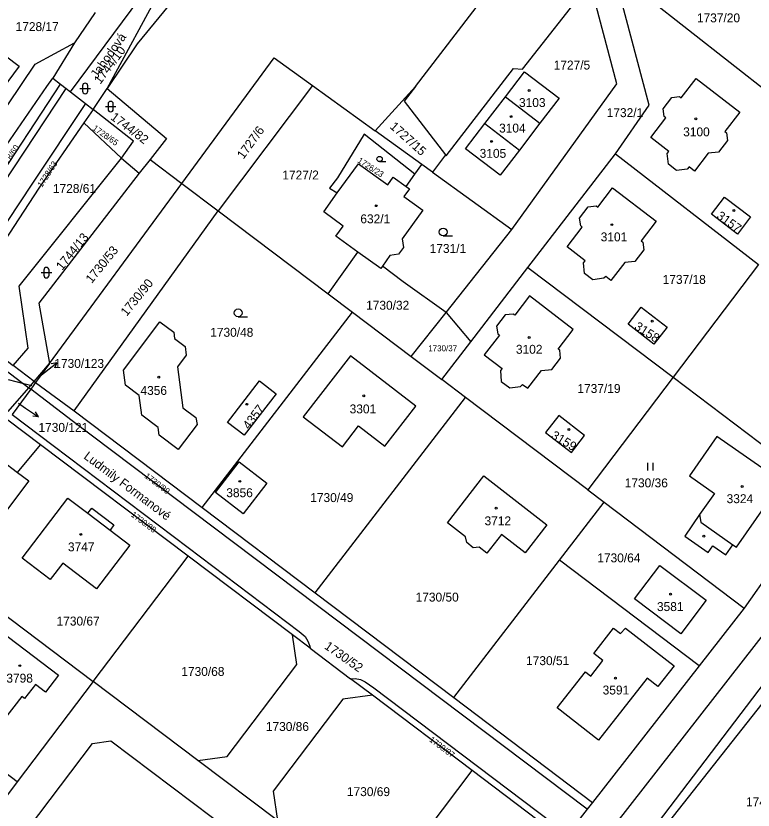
# Model space of a CAD drawing. Extents: x -679220 to -673243, y -1075091 to -1066557.
# Drawn here: x -677014 to -676873.4, y -1072325 to -1072173.6 of the extents above; entities that cross this region are included whole.
import ezdxf

# ---------------------------------------------------------------- set-up
doc = ezdxf.new("R2010")
doc.units = 0
for name, color, linetype in [('Hranice parcel', 7, 'Continuous'), ('Parcelní čísla', 7, 'Continuous'), ('Pop  PČ popisy', 7, 'Continuous'), ('Vnitřní kresba', 7, 'Continuous'), ('Značky budov', 7, 'Continuous'), ('Značky kultur', 7, 'Continuous')]:
    doc.layers.add(name, color=color, linetype=linetype)

msp = doc.modelspace()

# ---------------------------------------------------------------- linework, layer by layer
at = {"layer": 'Hranice parcel'}
for p, q in [((-676937.78, -1072187.06), (-676885.9, -1072119.34)), ((-676868.31, -1072190), (-676899.96, -1072165.14)), ((-676998.86, -1072172.9), (-677002.77, -1072178.71)), ((-677002.77, -1072178.71), (-677006.93, -1072185.42)), ((-677006.93, -1072185.42), (-677005.45, -1072186.58)), ((-677005.45, -1072186.58), (-677004.4, -1072187.4)), ((-677004.4, -1072187.4), (-677003.56, -1072188.05)), ((-677003.56, -1072188.05), (-677000.68, -1072190.31)), ((-676999.25, -1072191.43), (-676996.56, -1072187.43)), ((-676957.44, -1072186.84), (-676975.41, -1072210.74)), ((-676957.44, -1072186.84), (-676945.48, -1072195.49)), ((-676945.48, -1072195.49), (-676937.78, -1072187.06)), ((-676924.56, -1072194.1), (-676920.66, -1072189.01)), ((-676920.66, -1072189.01), (-676914.1, -1072194.06)), ((-677000.68, -1072190.31), (-676999.25, -1072191.43)), ((-676999.25, -1072191.43), (-677000.98, -1072193.99)), ((-677000.98, -1072193.99), (-676993.8, -1072200.73)), ((-676924.56, -1072194.1), (-676917.99, -1072199.15)), ((-676914.1, -1072194.06), (-676917.99, -1072199.15)), ((-676936.58, -1072201.92), (-676945.48, -1072195.49)), ((-676932.07, -1072200.1), (-676934.58, -1072203.37)), ((-676916.37, -1072221.57), (-676899.68, -1072199.86)), ((-676899.68, -1072199.86), (-676872.43, -1072221.01)), ((-676993.8, -1072200.73), (-676990.45, -1072203.57)), ((-676988.38, -1072200.94), (-676990.45, -1072203.57)), ((-676988.38, -1072200.94), (-676982.32, -1072205.52)), ((-676937.89, -1072203.74), (-676936.58, -1072201.92)), ((-676934.58, -1072203.37), (-676936.58, -1072201.92)), ((-676934.58, -1072203.37), (-676919.44, -1072214.32)), ((-676939.58, -1072206.09), (-676937.89, -1072203.74)), ((-677007.53, -1072239.86), (-676982.32, -1072205.52)), ((-676982.32, -1072205.52), (-676975.41, -1072210.74)), ((-677002.87, -1072248.9), (-676975.41, -1072210.74)), ((-676975.41, -1072210.74), (-676954.45, -1072226.57)), ((-676931.93, -1072230.12), (-676919.44, -1072214.32)), ((-676954.45, -1072226.57), (-676948.76, -1072218.62)), ((-676927.27, -1072235.75), (-676916.37, -1072221.57)), ((-676916.37, -1072221.57), (-676888.67, -1072242.5)), ((-676872.43, -1072221.01), (-676888.67, -1072242.5)), ((-676954.45, -1072226.57), (-676949.79, -1072230.09)), ((-676978.44, -1072267.35), (-676949.79, -1072230.09)), ((-676949.79, -1072230.09), (-676938.6, -1072238.55)), ((-676938.6, -1072238.55), (-676931.93, -1072230.12)), ((-676931.93, -1072230.12), (-676927.27, -1072235.75)), ((-676932.8, -1072242.93), (-676927.27, -1072235.75)), ((-676938.6, -1072238.55), (-676932.8, -1072242.93)), ((-677010.47, -1072243.28), (-677014.49, -1072240.22)), ((-677010.47, -1072243.28), (-677007.53, -1072239.86)), ((-677007.53, -1072239.86), (-677010.19, -1072243.49)), ((-676888.67, -1072242.5), (-676904.92, -1072263.99)), ((-676888.67, -1072242.5), (-676859.7, -1072264.4)), ((-677011.5, -1072244.49), (-677010.47, -1072243.28)), ((-677010.19, -1072243.49), (-677011.13, -1072244.77)), ((-677010.47, -1072243.28), (-677010.19, -1072243.49)), ((-677010.19, -1072243.49), (-677002.87, -1072248.9)), ((-676928.25, -1072246.37), (-676932.8, -1072242.93)), ((-677015.41, -1072249.05), (-677011.5, -1072244.49)), ((-677011.13, -1072244.77), (-677014.68, -1072249.6)), ((-677011.5, -1072244.49), (-677011.13, -1072244.77)), ((-676956.9, -1072283.63), (-676928.25, -1072246.37)), ((-676904.92, -1072263.99), (-676928.25, -1072246.37)), ((-677002.87, -1072248.9), (-676978.44, -1072267.35)), ((-677009.25, -1072255.35), (-677015.46, -1072250.66)), ((-677013.62, -1072260.65), (-677009.25, -1072255.35)), ((-676981.14, -1072276.59), (-677009.25, -1072255.35)), ((-676904.92, -1072263.99), (-676901.84, -1072266.32)), ((-676859.7, -1072264.4), (-676875.12, -1072286.5)), ((-676910.35, -1072277.39), (-676901.84, -1072266.32)), ((-676901.84, -1072266.32), (-676875.12, -1072286.5)), ((-676978.44, -1072267.35), (-676956.9, -1072283.63)), ((-676999.23, -1072300.52), (-676981.14, -1072276.59)), ((-676961.22, -1072291.64), (-676981.14, -1072276.59)), ((-676930.48, -1072303.58), (-676910.35, -1072277.39)), ((-676883.74, -1072297.55), (-676910.35, -1072277.39)), ((-677028.33, -1072278.52), (-676999.23, -1072300.52)), ((-676956.9, -1072283.63), (-676930.48, -1072303.58)), ((-676875.12, -1072286.5), (-676883.74, -1072297.55)), ((-676957.87, -1072294.17), (-676961.22, -1072291.64)), ((-676957.87, -1072294.17), (-676950.18, -1072299.98)), ((-676883.74, -1072297.55), (-676904.04, -1072323.56)), ((-677013.7, -1072319.67), (-677039.8, -1072299.95)), ((-676946.01, -1072303.12), (-676950.18, -1072299.98)), ((-676999.23, -1072300.52), (-677013.7, -1072319.67)), ((-676979.28, -1072315.59), (-676999.23, -1072300.52)), ((-676926.98, -1072317.5), (-676946.01, -1072303.12)), ((-676869.87, -1072302.33), (-676891.88, -1072330.24)), ((-676930.48, -1072303.58), (-676904.04, -1072323.56)), ((-676964.12, -1072327.04), (-676979.28, -1072315.59)), ((-676945.08, -1072341.44), (-676926.98, -1072317.5)), ((-676909.57, -1072330.65), (-676926.98, -1072317.5)), ((-677013.7, -1072319.67), (-677028.16, -1072338.82)), ((-676904.04, -1072323.56), (-676905.06, -1072324.86)), ((-676905.06, -1072324.86), (-676908.8, -1072329.65))]:
    msp.add_line(p, q, dxfattribs=at)
for points in [[(-677003.56, -1072188.05), (-676937.07, -1072098.47), (-676924.77, -1072082.25), (-676901.08, -1072050.53), (-676900.33, -1072051.15)], [(-676996.56, -1072187.43), (-676985.94, -1072167.77), (-676927.29, -1072088.05)], [(-676924.4, -1072090.21), (-676960.77, -1072142.26), (-676990.83, -1072178.91), (-676996.56, -1072187.43)], [(-676899.68, -1072199.86), (-676893.25, -1072190.57), (-676899.96, -1072165.14)], [(-676932.07, -1072200.1), (-676931.93, -1072200.28), (-676919.14, -1072183.61), (-676917.4, -1072183.73), (-676904.51, -1072167.26)], [(-676919.44, -1072214.32), (-676899.4, -1072186.54), (-676904.51, -1072167.26)], [(-677022.43, -1072175.06), (-677023.03, -1072175.85), (-677013.34, -1072183.15), (-677017.74, -1072189.03), (-677020.94, -1072186.65), (-677024.75, -1072191.65), (-677029.79, -1072187.85), (-677030, -1072188.09), (-677035.87, -1072183.69), (-677026.86, -1072171.73), (-677022.43, -1072175.06)], [(-677026.1, -1072206.25), (-677010.31, -1072182.77), (-677002.77, -1072178.71)], [(-676982.32, -1072205.52), (-676964.73, -1072181.57), (-676957.44, -1072186.84)], [(-676920.66, -1072189.01), (-676917, -1072184.22), (-676910.43, -1072189.26), (-676914.1, -1072194.06)], [(-677023.17, -1072209.06), (-677022.36, -1072209.08), (-677021.37, -1072208.84), (-677020.43, -1072208.43), (-677019.61, -1072207.8), (-677018.91, -1072207.08), (-677005.45, -1072186.58)], [(-677021.37, -1072206.38), (-677008.05, -1072187.02), (-677006.93, -1072185.42)], [(-676890.1, -1072193.02), (-676890.37, -1072192.78), (-676890.58, -1072191.29), (-676888.94, -1072189.16), (-676887.45, -1072188.97), (-676887.16, -1072189.21), (-676884.32, -1072185.52), (-676875.99, -1072191.91), (-676878.86, -1072195.65), (-676878.54, -1072195.88), (-676878.34, -1072197.36), (-676880.03, -1072199.55), (-676881.99, -1072199.74), (-676884.63, -1072203.18), (-676885.66, -1072202.38), (-676885.98, -1072202.79), (-676888.05, -1072203.05), (-676889.59, -1072201.87), (-676889.82, -1072199.8), (-676889.53, -1072199.42), (-676892.96, -1072196.78), (-676890.1, -1072193.02)], [(-677041.29, -1072239.09), (-677020.3, -1072211.54), (-677004.4, -1072187.4)], [(-676996.56, -1072187.43), (-676985.27, -1072196.98), (-676988.38, -1072200.94)], [(-676937.78, -1072187.06), (-676939.93, -1072189.86), (-676932.07, -1072200.1)], [(-676904.77, -1072334.29), (-676870.34, -1072290.1), (-676818.72, -1072215.8), (-676800.09, -1072189.36)], [(-677000.68, -1072190.31), (-677010.81, -1072205.46), (-677025.05, -1072227.04), (-677025.58, -1072227.92), (-677026.06, -1072228.81), (-677026.31, -1072229.79), (-677026.34, -1072230.8), (-677026.21, -1072231.82), (-677025.88, -1072232.78), (-677025.36, -1072233.67), (-677024.7, -1072234.47), (-677011.5, -1072244.49)], [(-676993.8, -1072200.73), (-676991.56, -1072197.46), (-676999.25, -1072191.43)], [(-677000.98, -1072193.99), (-677009.55, -1072206.46), (-677019.04, -1072220.85), (-677024.42, -1072229.04), (-677024.78, -1072230), (-677024.76, -1072230.97), (-677024.5, -1072231.92), (-677024.01, -1072232.8), (-677023.32, -1072233.51), (-677014.49, -1072240.22)], [(-676917.99, -1072199.15), (-676921.68, -1072203.94), (-676928.23, -1072198.9), (-676924.56, -1072194.1)], [(-676937.89, -1072203.74), (-676947.59, -1072196.14), (-676952.65, -1072204.47), (-676954.21, -1072206.43), (-676952.7, -1072207.35)], [(-677014.49, -1072240.22), (-677011.6, -1072236.95), (-677013.33, -1072225.14), (-676993.8, -1072200.73)], [(-676952.7, -1072207.35), (-676948.66, -1072201.76), (-676943.09, -1072205.77), (-676942.03, -1072204.31), (-676939.58, -1072206.09)], [(-676990.45, -1072203.57), (-677009.57, -1072228.38), (-677007.53, -1072239.86)], [(-676939.58, -1072206.09), (-676938.96, -1072206.54), (-676940.01, -1072207.99), (-676936.36, -1072210.64), (-676940.32, -1072216.11), (-676940.09, -1072217.74), (-676941.03, -1072219.03), (-676942.65, -1072219.3), (-676944.1, -1072221.31)], [(-676901.53, -1072223.27), (-676901.92, -1072223.61), (-676903.99, -1072223.94), (-676905.55, -1072222.71), (-676905.77, -1072220.66), (-676905.48, -1072220.26), (-676908.89, -1072217.63), (-676906.02, -1072213.86), (-676906.3, -1072213.62), (-676906.56, -1072212.15), (-676904.89, -1072210), (-676903.37, -1072209.8), (-676903.06, -1072210.02), (-676900.26, -1072206.35), (-676891.93, -1072212.75), (-676894.78, -1072216.47), (-676894.48, -1072216.72), (-676894.29, -1072218.2), (-676895.96, -1072220.4), (-676897.9, -1072220.58), (-676900.56, -1072224.01), (-676901.53, -1072223.27)], [(-676948.76, -1072218.62), (-676952.95, -1072215.6), (-676951.55, -1072213.67), (-676955.29, -1072210.94), (-676952.7, -1072207.35)], [(-676873.92, -1072211.88), (-676876.42, -1072215.19), (-676881.35, -1072211.4), (-676878.9, -1072208.15), (-676873.92, -1072211.88)], [(-676944.1, -1072221.31), (-676944.42, -1072221.76), (-676948.76, -1072218.62)], [(-676931.93, -1072230.12), (-676940.17, -1072224.32), (-676944.1, -1072221.31)], [(-676921.58, -1072241.22), (-676921.46, -1072243.29), (-676919.84, -1072244.51), (-676917.76, -1072244.27), (-676917.39, -1072243.87), (-676916.41, -1072244.6), (-676913.78, -1072241.23), (-676911.81, -1072241.02), (-676910.14, -1072238.87), (-676910.3, -1072237.35), (-676910.58, -1072237.12), (-676907.73, -1072233.39), (-676916.04, -1072226.98), (-676918.88, -1072230.64), (-676919.16, -1072230.44), (-676920.7, -1072230.61), (-676922.36, -1072232.73), (-676922.09, -1072234.21), (-676921.8, -1072234.44), (-676924.71, -1072238.2), (-676921.29, -1072240.84), (-676921.58, -1072241.22)], [(-676889.83, -1072232.95), (-676892.35, -1072236.18), (-676897.25, -1072232.37), (-676894.77, -1072229.1), (-676889.83, -1072232.95)], [(-676990.46, -1072245.98), (-676993.06, -1072244.01), (-676993.47, -1072241.13), (-676986.51, -1072231.94), (-676983.88, -1072233.91), (-676983.72, -1072235.09), (-676981.68, -1072236.65), (-676981.49, -1072238.27), (-676983.18, -1072240.51), (-676982.12, -1072248.29), (-676979.64, -1072250.17), (-676979.43, -1072251.49), (-676983.03, -1072256.26), (-676986.62, -1072253.51), (-676986.81, -1072252.06), (-676989.93, -1072249.74), (-676990.46, -1072245.98)], [(-676900.59, -1072339.27), (-676865.59, -1072293.33), (-676821.22, -1072232.97)], [(-676950.19, -1072238.42), (-676959.18, -1072250.03), (-676951.72, -1072255.78), (-676948.65, -1072251.77), (-676943.61, -1072255.64), (-676937.73, -1072248.01), (-676950.19, -1072238.42)], [(-676964.32, -1072245.64), (-676970.45, -1072253.56), (-676973.61, -1072251.11), (-676967.5, -1072243.19), (-676964.32, -1072245.64)], [(-676905.06, -1072324.86), (-676980.24, -1072268.15), (-677003.21, -1072250.78), (-677011.13, -1072244.77)], [(-677014.68, -1072249.6), (-677006.87, -1072255.49), (-676981.13, -1072274.94), (-676959.99, -1072291), (-676958.83, -1072291.96), (-676958.3, -1072292.81), (-676957.95, -1072293.75), (-676957.87, -1072294.17)], [(-676908.07, -1072256.82), (-676905.56, -1072253.61), (-676910.49, -1072249.76), (-676912.99, -1072253.05), (-676908.07, -1072256.82)], [(-676870.91, -1072266.7), (-676871.23, -1072266.48), (-676868.22, -1072262.25), (-676880.35, -1072253.8), (-676885.54, -1072261.32), (-676880.82, -1072264.69), (-676883.67, -1072268.69), (-676886.47, -1072272.81), (-676882, -1072275.9), (-676881.11, -1072274.65), (-676878.64, -1072276.36), (-676877.29, -1072274.43), (-676876.63, -1072274.89), (-676870.91, -1072266.7)], [(-677020.74, -1072269.31), (-677023.47, -1072267.21), (-677016.66, -1072258.36), (-677013.62, -1072260.65)], [(-676975.9, -1072264.49), (-676971.42, -1072258.62), (-676966.12, -1072262.67), (-676970.61, -1072268.54), (-676975.9, -1072264.49)], [(-677013.62, -1072260.65), (-677011.49, -1072262.26), (-677018.3, -1072271.19), (-677020.74, -1072269.31)], [(-676926.82, -1072274.99), (-676928, -1072274.03), (-676928.24, -1072272.95), (-676931.7, -1072270.27), (-676924.79, -1072261.29), (-676912.75, -1072270.63), (-676916.9, -1072275.97), (-676921.39, -1072272.46), (-676924.19, -1072276.03), (-676925.67, -1072274.92), (-676926.82, -1072274.99)], [(-677012.73, -1072276.99), (-677004.05, -1072265.54), (-677000.24, -1072268.42), (-676999.49, -1072267.43), (-676995.26, -1072270.64), (-676996.01, -1072271.63), (-676992.21, -1072274.5), (-676998.57, -1072282.86), (-677004.99, -1072277.95), (-677007.41, -1072281.08), (-677012.73, -1072276.99)], [(-676891.21, -1072278.38), (-676882.42, -1072285), (-676887.23, -1072291.4), (-676896.02, -1072284.77), (-676891.21, -1072278.38)], [(-677020.75, -1072295.82), (-677016.97, -1072290.85), (-677005.82, -1072299.3), (-677008.29, -1072302.54), (-677010.24, -1072301.07), (-677012.31, -1072303.76), (-677012.83, -1072303.35), (-677016.29, -1072307.91), (-677022.1, -1072303.49), (-677017.91, -1072297.98), (-677020.75, -1072295.82)], [(-676904.4, -1072299.48), (-676902.08, -1072296.5), (-676903.8, -1072295.15), (-676900.03, -1072290.31), (-676898.7, -1072291.34), (-676897.78, -1072290.34), (-676888.52, -1072297.55), (-676891.58, -1072301.47), (-676893.62, -1072299.88), (-676902.88, -1072311.7), (-676910.77, -1072305.54), (-676905.4, -1072298.69), (-676904.4, -1072299.48)], [(-676979.28, -1072315.59), (-676973.68, -1072314.81), (-676960.42, -1072297.25), (-676961.22, -1072291.64)], [(-676950.18, -1072299.98), (-676949.27, -1072299.96), (-676948.29, -1072300.16), (-676947.39, -1072300.57), (-676945.74, -1072301.71), (-676908.8, -1072329.65)], [(-676946.01, -1072303.12), (-676951.64, -1072303.88), (-676964.9, -1072321.44), (-676964.12, -1072327.04)], [(-677034.04, -1072358.2), (-676999.38, -1072312.31), (-676995.87, -1072311.82), (-676968.74, -1072332.31), (-676968.26, -1072335.81), (-677002.92, -1072381.7)]]:
    msp.add_lwpolyline(points, dxfattribs=at)
at = {"layer": 'Pop  PČ popisy'}
for p, q in [((-677008.49, -1072241.57), (-677006.12, -1072239.72)), ((-677006.12, -1072239.72), (-677007.22, -1072239.94)), ((-677006.12, -1072239.72), (-677006.61, -1072240.73)), ((-677009.45, -1072242.32), (-677008.49, -1072241.57)), ((-677012.42, -1072243.74), (-677015.33, -1072243.01)), ((-677010.9, -1072244.11), (-677012.42, -1072243.74)), ((-677013.48, -1072247.45), (-677012.13, -1072248.37)), ((-677012.13, -1072248.37), (-677009.64, -1072250.05)), ((-677009.64, -1072250.05), (-677010.75, -1072249.9)), ((-677009.64, -1072250.05), (-677010.19, -1072249.07))]:
    msp.add_line(p, q, dxfattribs=at)
at = {"layer": 'Vnitřní kresba'}
for p, q in [((-677000.24, -1072268.42), (-676996.01, -1072271.63)), ((-676883.67, -1072268.69), (-676883.4, -1072270.15)), ((-676883.4, -1072270.15), (-676877.29, -1072274.43))]:
    msp.add_line(p, q, dxfattribs=at)
at = {"layer": 'Značky budov'}
for centre in [(-676916.13, -1072187.81), (-676919.58, -1072192.78), (-676884.35, -1072193.21), (-676923.28, -1072197.5), (-676945.26, -1072209.78), (-676877.09, -1072210.68), (-676900.35, -1072213.39), (-676892.66, -1072231.8), (-676916.14, -1072234.91), (-676986.73, -1072242.46), (-676947.66, -1072246.03), (-676969.94, -1072247.64), (-676908.54, -1072252.46), (-676971.27, -1072262.34), (-676875.53, -1072263.31), (-676922.42, -1072267.44), (-677001.56, -1072272.46), (-676882.85, -1072272.8), (-676889.16, -1072283.85), (-677013.2, -1072297.49), (-676899.69, -1072299.87)]:
    msp.add_circle(centre, 0.175, dxfattribs=at)
at = {"layer": 'Značky kultur'}
for p, q in [((-677001.75, -1072187.41), (-676999.75, -1072187.41)), ((-677001.25, -1072186.91), (-677001.25, -1072187.91)), ((-677000.25, -1072187.91), (-677000.25, -1072186.91)), ((-676996.89, -1072190.87), (-676994.89, -1072190.87)), ((-676996.39, -1072190.37), (-676996.39, -1072191.37)), ((-676995.39, -1072191.37), (-676995.39, -1072190.37)), ((-676944.62, -1072201.37), (-676943.45, -1072201.37)), ((-676932.51, -1072215.54), (-676930.76, -1072215.54)), ((-677009.13, -1072222.54), (-677007.13, -1072222.54)), ((-677008.63, -1072222.04), (-677008.63, -1072223.04)), ((-677007.63, -1072223.04), (-677007.63, -1072222.04)), ((-676971.59, -1072230.96), (-676969.84, -1072230.96)), ((-676893.52, -1072260.29), (-676893.52, -1072258.79)), ((-676892.52, -1072260.29), (-676892.52, -1072258.79))]:
    msp.add_line(p, q, dxfattribs=at)
for centre, radius in [((-676944.63, -1072200.87), 0.502), ((-676932.51, -1072214.79), 0.75), ((-676971.59, -1072230.21), 0.75)]:
    msp.add_circle(centre, radius, dxfattribs=at)
for centre, start, end in [((-677000.75, -1072186.91), 0, 180), ((-677000.75, -1072187.91), 180, 359.9879), ((-676995.89, -1072190.37), 0, 180), ((-676995.89, -1072191.37), 180, 359.9879), ((-677008.13, -1072222.04), 0, 180), ((-677008.13, -1072223.04), 180, 359.9879)]:
    msp.add_arc(centre, 0.5, start, end, dxfattribs=at)

# ---------------------------------------------------------------- texts
at = {"layer": 'Parcelní čísla'}
for s, height, p in [('1737/20', 1.7, (-676884.15, -1072174.8)), ('1728/17', 1.7, (-677014.01, -1072176.47)), ('1727/5', 1.7, (-676911.45, -1072183.8)), ('3103', 1.7, (-676918.06, -1072190.95)), ('1732/1', 1.7, (-676901.34, -1072192.88)), ('3104', 1.7, (-676921.86, -1072195.82)), ('3100', 1.7, (-676886.77, -1072196.54)), ('3105', 1.7, (-676925.56, -1072200.64)), ('1727/2', 1.7, (-676963.17, -1072204.77)), ('1728/61', 1.7, (-677006.9, -1072207.35)), ('632/1', 1.7, (-676948.3, -1072213.13)), ('3101', 1.7, (-676902.49, -1072216.57)), ('1731/1', 1.7, (-676935.09, -1072218.78)), ('1737/18', 1.7, (-676890.68, -1072224.68)), ('1730/32', 1.7, (-676947.2, -1072229.61)), ('1730/48', 1.7, (-676976.91, -1072234.77)), ('1730/37', 1.14, (-676935.36, -1072237.53)), ('3102', 1.7, (-676918.65, -1072238.01)), ('1730/123', 1.7, (-677006.63, -1072240.7)), ('4356', 1.7, (-676990.21, -1072245.86)), ('1737/19', 1.7, (-676906.93, -1072245.48)), ('3301', 1.7, (-676950.34, -1072249.38)), ('1730/121', 1.7, (-677009.65, -1072252.9)), ('1730/36', 1.7, (-676897.91, -1072263.48)), ('3856', 1.7, (-676973.85, -1072265.36)), ('1730/49', 1.7, (-676957.85, -1072266.29)), ('3324', 1.7, (-676878.49, -1072266.5)), ('3712', 1.7, (-676924.63, -1072270.72)), ('3747', 1.7, (-677004.03, -1072275.69)), ('1730/64', 1.7, (-676903.14, -1072277.79)), ('1730/50', 1.7, (-676937.77, -1072285.27)), ('3581', 1.7, (-676891.77, -1072287.08)), ('1730/67', 1.7, (-677006.2, -1072289.84)), ('1730/51', 1.7, (-676916.71, -1072297.39)), ('1730/68', 1.7, (-676982.42, -1072299.45)), ('3798', 1.7, (-677015.77, -1072300.72)), ('3591', 1.7, (-676902.12, -1072302.99)), ('1730/86', 1.7, (-676966.31, -1072309.95)), ('1730/69', 1.7, (-676950.86, -1072322.37)), ('1744/16', 1.7, (-676874.79, -1072324.3))]:
    msp.add_text(s, height=height, dxfattribs=at).set_placement(p)
for s, height, rotation, p in [('1744/10', 1.7, 53, (-676997.87, -1072186.72)), ('1744/82', 1.7, 323, (-676996.05, -1072193.18)), ('1727/15', 1.7, 318, (-676942.8, -1072194.86)), ('1728/65', 1.14, 325, (-676999.45, -1072195.24)), ('1727/6', 1.7, 54, (-676970.58, -1072201.01)), ('1728/60', 1.14, 57, (-677016.26, -1072203.25)), ('1728/63', 1.14, 57, (-677008.98, -1072206.37)), ('1726/23', 1.14, 327, (-676948.94, -1072201.43)), ('3157', 1.7, 324, (-676880.55, -1072212.05)), ('1744/13', 1.7, 51, (-677005.14, -1072222.23)), ('1730/53', 1.7, 51, (-676999.5, -1072224.7)), ('1730/90', 1.7, 51, (-676992.83, -1072230.98)), ('3158', 1.7, 327, (-676896.22, -1072233.2)), ('4357', 1.7, 53, (-676969.51, -1072252.58)), ('3159', 1.7, 329, (-676912.09, -1072254.02)), ('1730/89', 1.14, 323, (-676989.54, -1072261.56)), ('1730/88', 1.14, 323, (-676992.13, -1072268.92)), ('1730/52', 1.7, 325, (-676955.3, -1072294.12)), ('1730/87', 1.14, 323, (-676935.27, -1072311.83))]:
    msp.add_text(s, height=height, rotation=rotation, dxfattribs=at).set_placement(p)
at = {"layer": 'Pop  PČ popisy'}
for s, rotation, p in [('Jahodová', 55, (-676998.48, -1072185.66)), ('Ludmily Formanové', 323, (-677001.16, -1072257.87))]:
    msp.add_text(s, height=1.7, rotation=rotation, dxfattribs=at).set_placement(p)

doc.saveas('drawing.dxf')
